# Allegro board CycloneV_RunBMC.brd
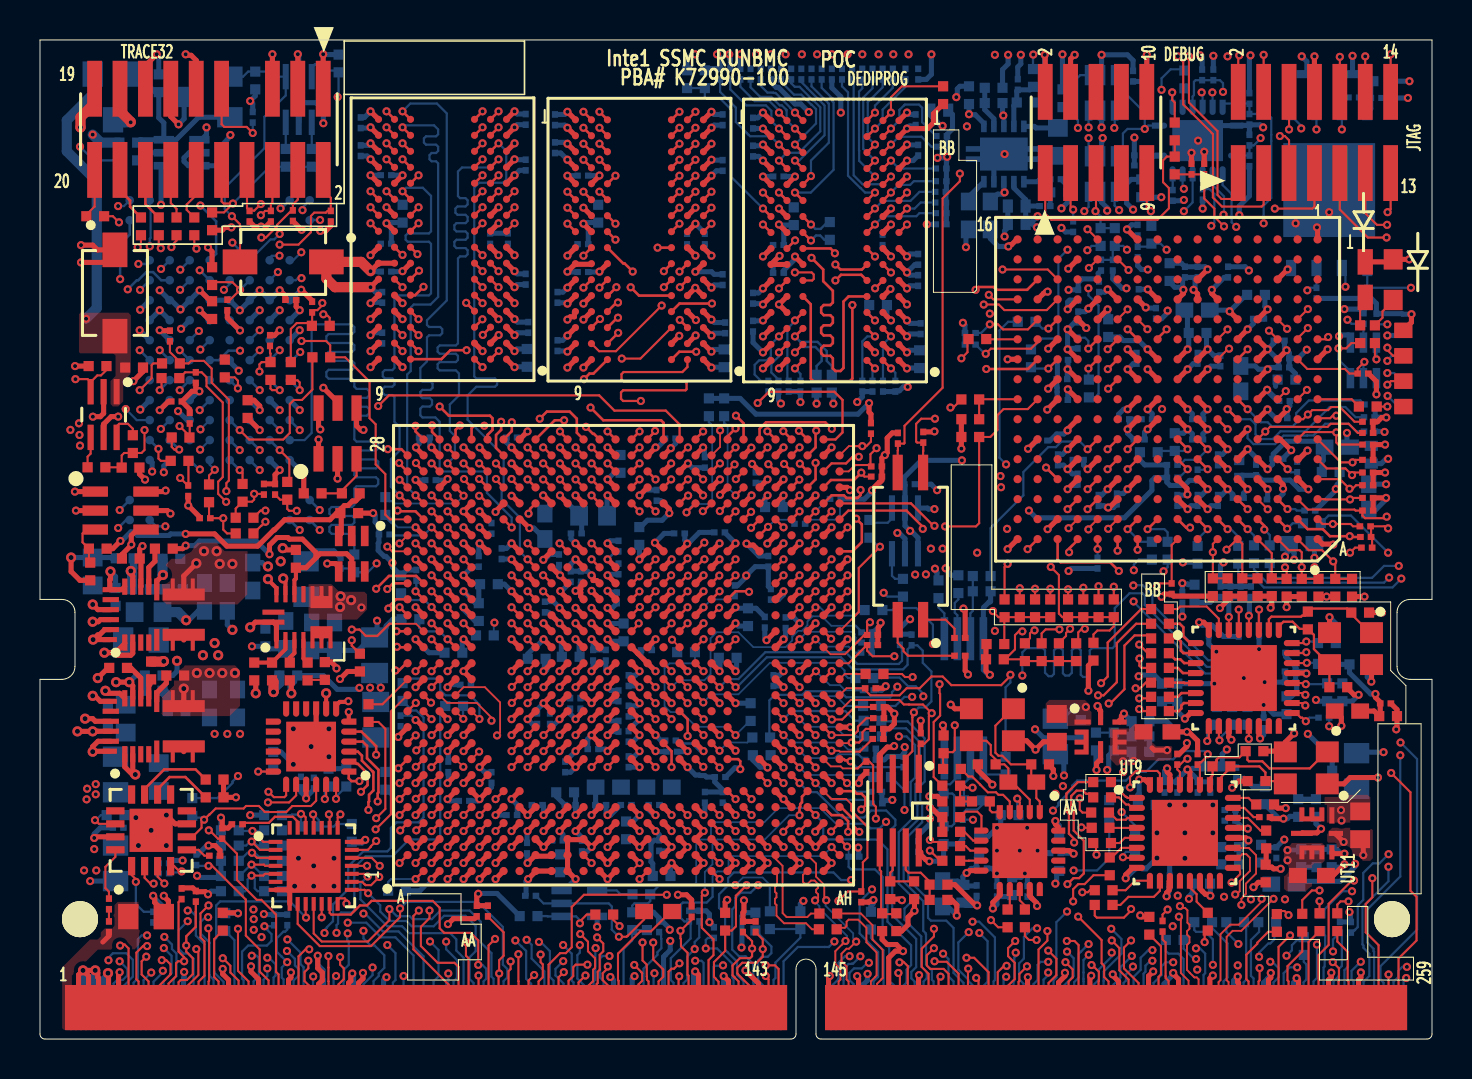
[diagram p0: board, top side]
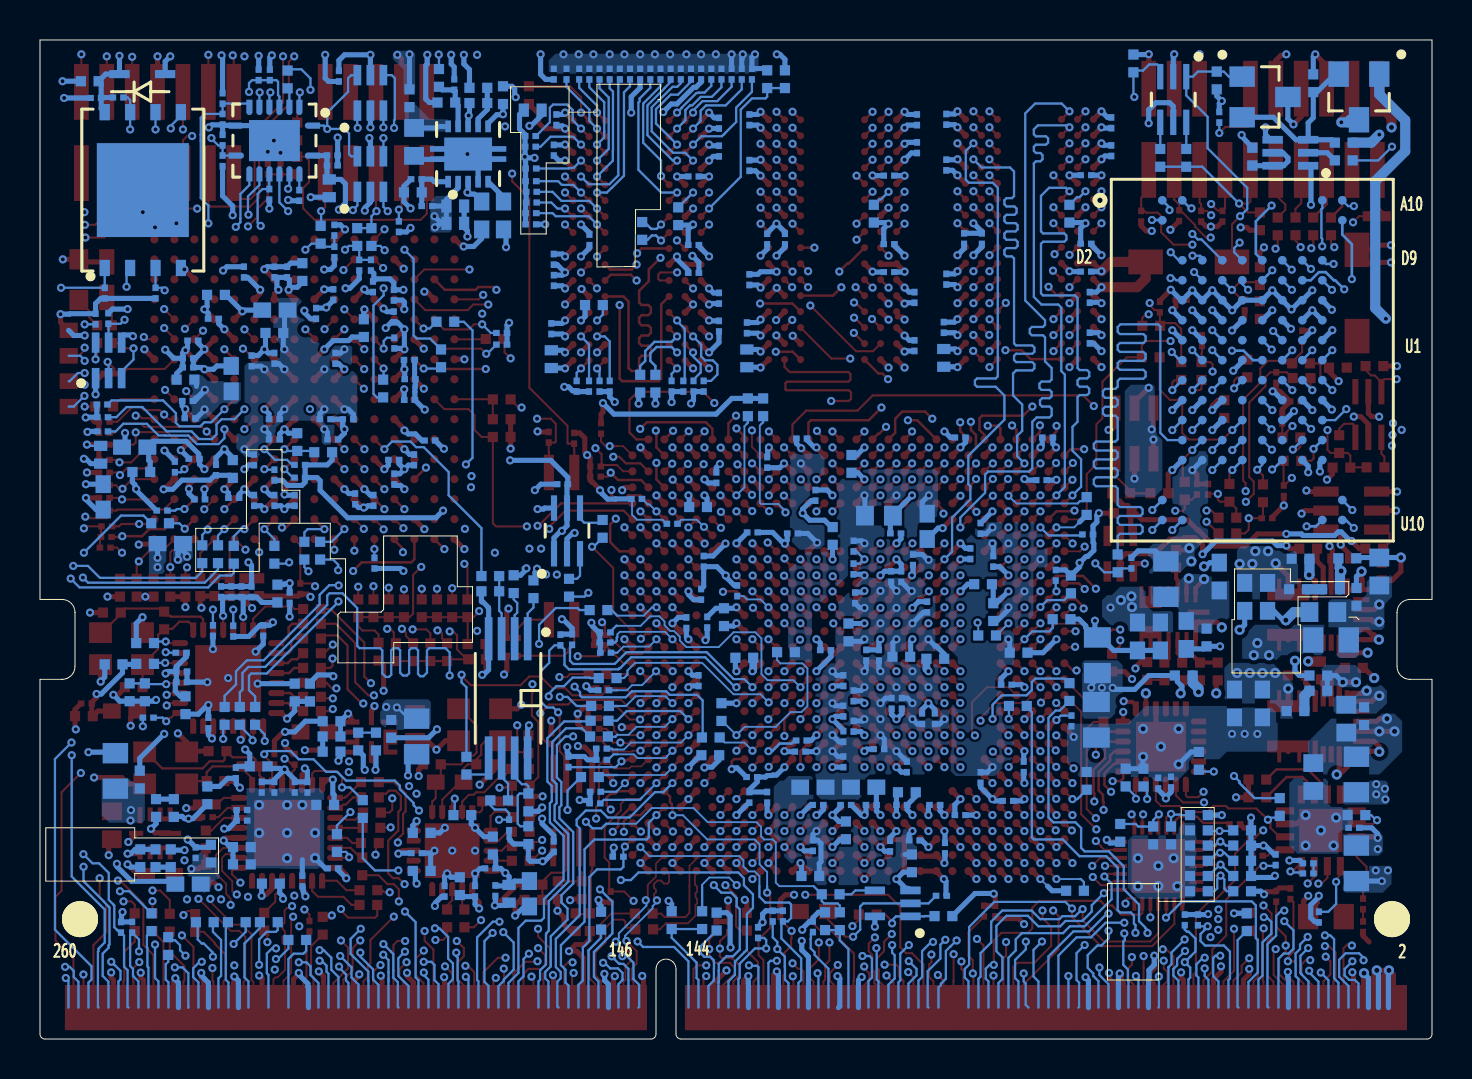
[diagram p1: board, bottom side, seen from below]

Outline 69.6 x 50 mm; copper layers: TOP, L2-GND, L3-SIG, L4-GND, L5-SIG, L6-VCC, L7-VCC, L8-SIG, L9-GND, L10-SIG, L11-GND, BOTTOM. Coordinates in mm from the lower left corner of the outline.
Outline path: 0,50 0,22 1.1,22 arc(1.56,21.81) 1.75,21.35 1.75,18.65 arc(1.56,18.19) 1.1,18 0,18 0,0.25 arc(0.07,0.07) 0.25,0 37.55,0 arc(37.73,0.07) 37.8,0.25 37.8,3.5 arc(38.3,4) 38.8,3.5 38.8,0.25 arc(38.87,0.07) 39.05,0 69.35,0 arc(69.53,0.07) 69.6,0.25 69.6,18 68.5,18 arc(68.04,18.19) 67.85,18.65 67.85,21.35 arc(68.04,21.81) 68.5,22 69.6,22 69.6,50 0,50

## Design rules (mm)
constraint set DEFAULT: min track width 0.104
net group CLK_100M_BMC_PE_D: nets CLK_100M_BMC_PE_DN CLK_100M_BMC_PE_DP
net group DIFFPAIR0: nets P2E_PCH_BMC_TX_DN P2E_PCH_BMC_TX_DP
net group DIFFPAIR1: nets P2E_PCH_BMC_RX_C_DN P2E_PCH_BMC_RX_C_DP
net group DIFFPAIR2: nets P2E_PCH_BMC_RX_DN P2E_PCH_BMC_RX_DP
net group EMMC_SMC_DAT1: nets EMMC_SMC_DAT1 EMMC_SMC_DAT1_R
net group EMMC_SMC_DAT2: nets EMMC_SMC_DAT2 EMMC_SMC_DAT2_R
net group EMMC_SMC_DAT3: nets EMMC_SMC_DAT3 EMMC_SMC_DAT3_R
net group EMMC_SMC_DAT4: nets EMMC_SMC_DAT4 EMMC_SMC_DAT4_R
net group EMMC_SMC_DAT5: nets EMMC_SMC_DAT5 EMMC_SMC_DAT5_R
net group EMMC_SMC_DAT6: nets EMMC_SMC_DAT6 EMMC_SMC_DAT6_R
net group EMMC_SMC_DAT7: nets EMMC_SMC_DAT7 EMMC_SMC_DAT7_R
net group FM_C5_FPGA_AS_DATA0: nets FM_C5_FPGA_AS_DATA0 FM_C5_FPGA_AS_DATA0_R
net group FM_C5_FPGA_DCLK: nets FM_C5_FPGA_DCLK FM_C5_FPGA_DCLK_R
net group IRQ_SMB_INTERNAL_ALERT_N: nets IRQ_SMB_INTERNAL_ALERT_N IRQ_SMB_INTERNAL_ALERT_R_N
net group JTAG_C5_FPGA_TDO: nets JTAG_C5_FPGA_TDO JTAG_C5_FPGA_TDO_R
net group JTAG_HDR_TDI: nets JTAG_HDR_TDI JTAG_M10_TDI
net group JTAG_M10_MASTER_TCK: nets JTAG_M10_MASTER_TCK JTAG_M10_MASTER_TCK_R
net group JTAG_M10_MASTER_TDI: nets JTAG_M10_MASTER_TDI JTAG_M10_MASTER_TDI_R
net group JTAG_M10_MASTER_TMS: nets JTAG_M10_MASTER_TMS JTAG_M10_MASTER_TMS_R
net group JTAG_M10_TDO: nets JTAG_M10_TDO JTAG_M10_TDO_R
net group PD_BMC_DDR3_DQS5: nets PD_BMC_DDR3_DQS5_P PU_BMC_DDR3_DQS5_N
net group RGMII_BMC_RMM4_MDC: nets RGMII_BMC_RMM4_MDC RGMII_BMC_RMM4_R_MDC
net group RGMII_BMC_RMM4_MDIO: nets RGMII_BMC_RMM4_MDIO RGMII_BMC_RMM4_R_MDIO
net group RGMII_BMC_RMM4_R_TXD_0: nets RGMII_BMC_RMM4_R_TXD_0 RGMII_BMC_RMM4_TXD_0
net group RGMII_BMC_RMM4_R_TXD_1: nets RGMII_BMC_RMM4_R_TXD_1 RGMII_BMC_RMM4_TXD_1
net group RGMII_BMC_RMM4_R_TXD_2: nets RGMII_BMC_RMM4_R_TXD_2 RGMII_BMC_RMM4_TXD_2
net group RGMII_BMC_RMM4_R_TXD_3: nets RGMII_BMC_RMM4_R_TXD_3 RGMII_BMC_RMM4_TXD_3
net group RGMII_BMC_RMM4_TX_CLK: nets RGMII_BMC_RMM4_TX_CLK RGMII_BMC_RMM4_TX_R_CLK
net group RGMII_BMC_RMM4_TX_CTRL: nets RGMII_BMC_RMM4_TX_CTRL RGMII_BMC_RMM4_TX_R_CTRL
net group SMB_C5_M10_CLK: nets SMB_C5_M10_CLK SMB_C5_M10_R_CLK
net group SMB_C5_M10_DATA: nets SMB_C5_M10_DATA SMB_C5_M10_R_DATA
net group SPI_M10_FLASH_CLK: nets SPI_M10_FLASH_CLK SPI_M10_FLASH_CLK_R
net group SPI_M10_FLASH_MISO: nets SPI_M10_FLASH_MISO SPI_M10_FLASH_MISO_R
net group SPI_M10_FLASH_MOSI: nets SPI_M10_FLASH_MOSI SPI_M10_FLASH_MOSI_R
net group TP_EMMC_STRB: nets EMMC_STRB_R TP_EMMC_STRB
net group TRC_HPS_TRACE32_D0: nets TRC_HPS_TRACE32_D0 TRC_HPS_TRACE32_D0_R
net group TRC_HPS_TRACE32_D1: nets TRC_HPS_TRACE32_D1 TRC_HPS_TRACE32_D1_R
net group TRC_HPS_TRACE32_D2: nets TRC_HPS_TRACE32_D2 TRC_HPS_TRACE32_D2_R
net group TRC_HPS_TRACE32_D3: nets TRC_HPS_TRACE32_D3 TRC_HPS_TRACE32_D3_R
net group TRC_TRACE32_CLK: nets TRC_TRACE32_CLK TRC_TRACE32_CLK_R
net group ULPI_USBPHY_PCH_CLKOUT: nets ULPI_USBPHY_PCH_CLKOUT ULPI_USBPHY_PCH_CLKOUT_R
net group ULPI_USBPHY_PCH_DATA<0>: nets ULPI_USBPHY_PCH_DATA<0> ULPI_USBPHY_PCH_R_DATA<0>
net group ULPI_USBPHY_PCH_DATA<1>: nets ULPI_USBPHY_PCH_DATA<1> ULPI_USBPHY_PCH_R_DATA<1>
net group ULPI_USBPHY_PCH_DATA<2>: nets ULPI_USBPHY_PCH_DATA<2> ULPI_USBPHY_PCH_R_DATA<2>
net group ULPI_USBPHY_PCH_DATA<3>: nets ULPI_USBPHY_PCH_DATA<3> ULPI_USBPHY_PCH_R_DATA<3>
net group ULPI_USBPHY_PCH_DATA<4>: nets ULPI_USBPHY_PCH_DATA<4> ULPI_USBPHY_PCH_R_DATA<4>
net group ULPI_USBPHY_PCH_DATA<5>: nets ULPI_USBPHY_PCH_DATA<5> ULPI_USBPHY_PCH_R_DATA<5>
net group ULPI_USBPHY_PCH_DATA<6>: nets ULPI_USBPHY_PCH_DATA<6> ULPI_USBPHY_PCH_R_DATA<6>
net group ULPI_USBPHY_PCH_DATA<7>: nets ULPI_USBPHY_PCH_DATA<7> ULPI_USBPHY_PCH_R_DATA<7>
net group ULPI_USBPHY_PCH_DIR: nets ULPI_USBPHY_PCH_DIR ULPI_USBPHY_PCH_DIR_R
net group ULPI_USBPHY_PCH_NXT: nets ULPI_USBPHY_PCH_NXT ULPI_USBPHY_PCH_NXT_R
net group ULPI_USBPHY_USB2B_CLKOUT: nets ULPI_USBPHY_USB2B_CLKOUT ULPI_USBPHY_USB2B_CLKOUT_R
net group ULPI_USBPHY_USB2B_DATA<0>: nets ULPI_USBPHY_USB2B_DATA<0> ULPI_USBPHY_USB2B_R_DATA<0>
net group ULPI_USBPHY_USB2B_DATA<1>: nets ULPI_USBPHY_USB2B_DATA<1> ULPI_USBPHY_USB2B_R_DATA<1>
net group ULPI_USBPHY_USB2B_DATA<2>: nets ULPI_USBPHY_USB2B_DATA<2> ULPI_USBPHY_USB2B_R_DATA<2>
net group ULPI_USBPHY_USB2B_DATA<3>: nets ULPI_USBPHY_USB2B_DATA<3> ULPI_USBPHY_USB2B_R_DATA<3>
net group ULPI_USBPHY_USB2B_DATA<4>: nets ULPI_USBPHY_USB2B_DATA<4> ULPI_USBPHY_USB2B_R_DATA<4>
net group ULPI_USBPHY_USB2B_DATA<5>: nets ULPI_USBPHY_USB2B_DATA<5> ULPI_USBPHY_USB2B_R_DATA<5>
net group ULPI_USBPHY_USB2B_DATA<6>: nets ULPI_USBPHY_USB2B_DATA<6> ULPI_USBPHY_USB2B_R_DATA<6>
net group ULPI_USBPHY_USB2B_DATA<7>: nets ULPI_USBPHY_USB2B_DATA<7> ULPI_USBPHY_USB2B_R_DATA<7>
net group ULPI_USBPHY_USB2B_DIR: nets ULPI_USBPHY_USB2B_DIR ULPI_USBPHY_USB2B_DIR_R
net group ULPI_USBPHY_USB2B_NXT: nets ULPI_USBPHY_USB2B_NXT ULPI_USBPHY_USB2B_NXT_R
net group USB2_PCH_SMC: nets USB2_PCH_SMC_DN USB2_PCH_SMC_DP
net group USB2_USB2B_D: nets USB2_USB2B_DN USB2_USB2B_DP
net group BANK-3B: nets CLK_50M_C5_FPGA DBG_XDP_SYSPWROK_HOOK3 DBP_DEBUG_EN_N DBP_JUMPER_EN_DET DBP_PRDY_N DBP_PREQ_N DBP_PWR_DEBUG_HOOK2_N DBP_SMC_NTRST_N DBP_SMC_TCK_R DBP_SMC_TDI_R DBP_SMC_TDO DBP_SMC_TMS_R DBP_TCK_MUX_SEL DBP_XDP_PRSNT_N FM_BMC_PWRBTN_OUT_N FM_LED_BEEP_BMC FM_TPM_EN_PULSE FP_ID_BTN_N FP_ID_LED_N FP_LED_STATUS_AMBER_N FP_LED_STATUS_GREEN_N FP_NMI_BTN_N FP_PWR_BTN_N FP_RST_BTN_N RST_BMC_RSTBTN_OUT_N
net group BANK-4A: nets FM_BIOS_POST_CMPLT_N FM_BMC_ONCTL_R_N FM_CPU_BMC_MSMI_CATERR_LVT3_N FM_CPU_BMCINIT FM_CPU_ERR2_LVT3_N FM_PCH_BMC_THERMTRIP_N FM_PVCCIN_CPU0_PWR_IN_ALERT_N FM_PVCCIN_CPU1_PWR_IN_ALERT_N FM_SLPS4_N IRQ_BMC_PCH_NMI IRQ_BMC_PCH_SCI_LPC_R_N IRQ_BMC_PCH_SMI_LPC_N IRQ_NMI_EVENT_N IRQ_SMI_ACTIVE_N PECI_SMC_IN_LVC33 PECI_SMC_OUT_N PWRGD_CPU0_LVC3 PWRGD_PS_PWROK_PLD_BMC RST_PLTRST_MONITOR_N RST_SMC_SMB_MUX_RST_N SGPIO_SMC_CPLD_CLK SGPIO_SMC_CPLD_DIN SGPIO_SMC_CPLD_LD_N SMB_BATPAK_DATA SMB_BMC2BMC_CLK SMB_BMC2BMC_DATA SMB_HOST_LVC3_CLK SMB_HSBP_LVC3_CLK SMB_HSBP_LVC3_DATA SMB_IPMB_LVC3_DATA SMB_PCIE_LVC3_CLK SMB_PCIE_LVC3_DATA SMB_PMBUS_LVC3_CLK SMB_PMBUS_LVC3_DATA SMB_RSSD_15_8_CLK SMB_RSSD_15_8_DATA SMB_SMLINK0_LVC3_CLK SMB_SMLINK0_LVC3_DATA SMB_TEMP_SENSOR_LVC3_CLK SMB_TEMP_SENSOR_LVC3_DATA
net group CLK: nets CLK_25M_HPS_CLK1 CLK_25M_HPS_CLK1_R CLK_25M_HPS_CLK2 CLK_25M_HPS_CLK2_R CLK_25M_M10 CLK_25M_M10_R CLK_50M_C5_FPGA_R
net group DDR_ADD: nets V_M_BMC_DDR3_RST_N
net group EMMC_SMC_CLK: nets EMMC_SMC_CLK EMMC_SMC_CLK_CONN EMMC_SMC_CLK_R
net group EMMC_SMC_CMD: nets EMMC_SMC_CMD EMMC_SMC_CMD_CONN EMMC_SMC_CMD_R
net group EMMC_SMC_DAT0_R: nets EMMC_SMC_DAT0 EMMC_SMC_DAT0_CONN EMMC_SMC_DAT0_R
net group EU9: nets ISENSE_P3V3_N ISENSE_P3V3_P ISENSE_P12V_C ISENSE_P12V_N ISENSE_P12V_P PD_TELEMETRY_ADDR PU_TELEMETRY_ENA PU_TELEMETRY_SHTDN
net group FM_C5_M10_RSVD: nets FM_C5_M10_RSVD<0> FM_C5_M10_RSVD<1> FM_C5_M10_RSVD<2> FM_C5_M10_RSVD<3>
net group FM_M10_EDGE_RSVD: nets DBG_RSMRST_MONITOR_N FM_M10_EDGE_RSVD<2> FM_M10_EDGE_RSVD<3> FM_M10_EDGE_RSVD<4> FM_M10_EDGE_RSVD<5> FM_M10_EDGE_RSVD<6> FM_M10_EDGE_RSVD<7>
net group FM_VGA_B: nets FM_VGA_B<0> FM_VGA_B<1> FM_VGA_B<2> FM_VGA_B<3>
net group FM_VGA_G: nets FM_VGA_G<0> FM_VGA_G<1> FM_VGA_G<2> FM_VGA_G<3>
net group FM_VGA_R: nets FM_VGA_R<0> FM_VGA_R<1> FM_VGA_R<2> FM_VGA_R<3>
net group JTAG_HDR_SW_TCK: nets JTAG_HDR_SW_TCK JTAG_HDR_TCK JTAG_M10_TCK
net group JTAG_HDR_SW_TMS: nets JTAG_HDR_SW_TMS JTAG_HDR_TMS JTAG_M10_TMS
net group NC_EMMC: nets NC_EMMC<0> NC_EMMC<1> NC_EMMC<2> NC_EMMC<3> NC_EMMC<4> NC_EMMC<5> NC_EMMC<6> NC_EMMC<7> NC_EMMC<8> NC_EMMC<9> NC_EMMC<10> NC_EMMC<11>
net group NC_EMMC_RFU: nets NC_EMMC_RFU<0> NC_EMMC_RFU<1> NC_EMMC_RFU<2> NC_EMMC_RFU<3> NC_EMMC_RFU<4> NC_EMMC_RFU<5> NC_EMMC_RFU<6> NC_EMMC_RFU<7> NC_EMMC_RFU<8> NC_EMMC_RFU<9> NC_EMMC_RFU<10> NC_EMMC_RFU<11> NC_EMMC_RFU<12> NC_EMMC_RFU<13> NC_EMMC_RFU<14> NC_EMMC_RFU<15> NC_EMMC_RFU<16> NC_EMMC_RFU<17> NC_EMMC_RFU<18> NC_EMMC_RFU<19> NC_EMMC_RFU<20> NC_EMMC_RFU<21> NC_EMMC_RFU<22> NC_EMMC_RFU<23> NC_EMMC_RFU<24> NC_EMMC_RFU<25> NC_EMMC_RFU<26> NC_EMMC_RFU<27> NC_EMMC_RFU<28> NC_EMMC_RFU<29> NC_EMMC_RFU<30> NC_EMMC_RFU<31> NC_EMMC_RFU<32> NC_EMMC_RFU<33> NC_EMMC_RFU<34> NC_EMMC_RFU<35> NC_EMMC_RFU<36> NC_EMMC_RFU<37> NC_EMMC_RFU<38> NC_EMMC_RFU<39> NC_EMMC_RFU<40> NC_EMMC_RFU<41>
net group PD_V_M_DDR3_DQU: nets PD_V_M_DDR3_DQU<0> PD_V_M_DDR3_DQU<1> PD_V_M_DDR3_DQU<2> PD_V_M_DDR3_DQU<3> PD_V_M_DDR3_DQU<4> PD_V_M_DDR3_DQU<5> PD_V_M_DDR3_DQU<6> PD_V_M_DDR3_DQU<7>
net group PECI_SMC_S_R: nets PECI_SMC PECI_SMC_IN PECI_SMC_OUT_B PECI_SMC_S_R
net group PWRGD_SMC_AUX_VRS_R2: nets PWRGD_BMC_AUX_VRS PWRGD_P0V75_AUX_R PWRGD_SMC_AUX_VRS_R2
net group RMII: nets RMII_BMC_NIC_TX_EN RMII_BMC_NIC_TX_R_EN RMII_BMC_NIC_TXD_0 RMII_BMC_NIC_TXD_0_R RMII_BMC_NIC_TXD_1 RMII_BMC_NIC_TXD_1_R RMII_NIC_BMC_CRS_DV RMII_NIC_BMC_CRS_R_DV RMII_NIC_BMC_RXD_0 RMII_NIC_BMC_RXD_1 RMII_NIC_BMC_RXD_R_0 RMII_NIC_BMC_RXD_R_1
net group RST_EMMC_SMC_R_N: nets RST_EMMC_SMC_R_N RST_HPS_RST_N RST_HPS_RST_R1_N RST_HPS_RST_R2_N
net group SMB_INTERNAL_CLK_R2: nets SMB_INTERNAL_CLK SMB_INTERNAL_CLK_R2 SMB_INTERNAL_R_CLK
net group SMB_INTERNAL_DATA: nets SMB_INTERNAL_DATA SMB_INTERNAL_DATA_R2 SMB_INTERNAL_R_DATA
net group SPI_M10_FLASH_CS0_N: nets FM_DEDI_IO3 FM_M10_DEV_CLR_N P3V3_AUX_SPI SPI_M10_FLASH_CS0__RN SPI_M10_FLASH_CS0_N SPI_M10_FLASH_IO2_WP_N SPI_M10_FLASH_IO2_WP_R_N SPI_M10_FLASH_IO3_HD_N SPI_M10_FLASH_IO3_HD_R_N

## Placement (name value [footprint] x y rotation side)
C1A6  0.1uF  [SMC0201A]  45.32 40.77 90 bottom
C1A7  0.1uF  [SMC0201A]  39.59 48.56 180 bottom
C1A8  0.1uF  [SMC0201A]  36.54 48.56 180 bottom
C2L16  0.1uF  [SMC0201A]  56.48 7.64 0 bottom
C2L17  2.2uF  [SMC0402A]  54.9 11.71 270 bottom
C2L18  0.1uF  [SMC0201A]  54.69 8.54 270 bottom
C2L24  0.1uF  [SMC0201A]  56.86 12.87 180 bottom
C2L25  0.1uF  [SMC0201A]  57.88 12.87 180 bottom
C2L26  0.1uF  [SMC0201A]  58.51 12.87 180 bottom
C2L31  0.1uF  [SMC0201A]  56.23 12.87 180 bottom
C2L34  0.1uF  [SMC0201A]  59.81 13.58 180 bottom
C3L11  2.2uF  [SMC0402A]  61.28 8.73 0 top
C5C1  0.1uF  [SMC0201A]  46.82 8.54 270 bottom
C5C2  0.1uF  [SMC0201A]  46.83 7.69 180 bottom
C5C5  NA  [SMC0402A]  49.56 13.75 90 top
C5C6  NA  [SMC0402A]  47.78 13.75 270 top
C5C7  10uF  [SMC0402B]  46.15 7.71 270 bottom
C5C8  0.1uF  [SMC0201A]  47.85 7.13 0 bottom
C5C13  0.1uF  [SMC0201A]  49.37 7.13 0 bottom
C5N17  0.1uF  [SMC0201A]  51.03 9.3 90 bottom
C7A14  2.2uF  [SMC0402A]  59.95 9.61 90 bottom
C7A15  1.0uF  [SMC0402A]  59.95 8.74 90 bottom
C7A16  22.0pF  [SMC0402A]  61.27 12.91 270 top
C7A17  22.0pF  [SMC0402A]  60.28 14.41 90 top
C8A30  0.1uF  [SMC0201A]  59.77 10.93 90 bottom
C8A31  0.1uF  [SMC0201A]  59.77 11.46 90 bottom
C8A32  2.2uF  [SMC0402A]  61.23 11.75 0 bottom
C8F1  10uF  [SMC0402B]  49.28 40.82 180 bottom
C8F2  22uF  [SMC0603A]  47.52 41.92 180 bottom
C8F3  10uF  [SMC0402B]  49.28 41.69 180 bottom
C8F4  1.0uF  [SMC0402A]  50.51 42.37 270 bottom
C8F5  4.7uF  [SMC0603C]  50.89 45.6 270 bottom
C8F6  0.1uF  [SMC0402A]  46.45 46.79 0 bottom
C8F7  1000pF  [SMC0402A]  48.84 46.87 270 bottom
C8F8  1000pF  [SMC0402A]  47.24 46.84 270 bottom
C9L13  0.1uF  [SMC0201A]  43.91 48.56 180 bottom
C107  10uF  [SMC0603C]  50.84 16.27 270 top
C114  10uF  [SMC0603C]  66.01 11.4 270 top
C305  2.2uF  [SMC0402A]  65.47 18.75 270 bottom
C306  22.0pF  [SMC0402A]  64.47 17.61 90 top
C307  22.0pF  [SMC0402A]  65.56 21.34 90 top
C308  0.1uF  [SMC0201A]  57.12 22.36 180 bottom
C309  0.1uF  [SMC0201A]  62.78 17.86 90 bottom
C310  0.1uF  [SMC0201A]  62.78 18.4 90 bottom
C311  2.2uF  [SMC0402A]  62.32 17.15 180 bottom
C312  0.1uF  [SMC0201A]  59.02 22.12 0 bottom
C313  0.1uF  [SMC0201A]  59.53 22.12 0 bottom
C314  0.1uF  [SMC0201A]  60.04 22.12 0 bottom
C315  0.1uF  [SMC0201A]  60.55 22.12 0 bottom
C316  0.1uF  [SMC0201A]  61.18 15.55 0 bottom
C317  0.1uF  [SMC0201A]  58.44 20.71 180 bottom
C318  2.2uF  [SMC0402A]  56.86 16.9 0 bottom
C319  1.0uF  [SMC0402A]  64.36 17.8 180 bottom
C320  2.2uF  [SMC0402A]  65.12 17.8 180 bottom
C321  1.0uF  [SMC0402A]  66.96 16.16 90 top
C322  0.1uF  [SMC0201A]  67.01 16.79 90 top
CB1  0.1uF  [SMC0402A]  5.94 47.39 0 bottom
CB2  10pF  [SMC0201A]  54.88 40.21 0 bottom
CB3  10uF  [SMC0402B]  45.41 46.49 180 bottom
CB4  0.1uF  [SMC0201A]  24.29 45.76 0 bottom
CB5  0.1uF  [SMC0201A]  43.78 45.74 0 bottom
CB6  0.1uF  [SMC0201A]  34.13 45.74 0 bottom
CB7  0.1uF  [SMC0201A]  25.75 45.74 0 bottom
CB8  0.1uF  [SMC0201A]  16.04 45.59 0 bottom
CB9  0.1uF  [SMC0201A]  35.65 45.57 0 bottom
CB10  0.1uF  [SMC0201A]  25.75 44.34 0 bottom
CB11  0.1uF  [SMC0201A]  43.91 44.21 0 bottom
CB12  0.1uF  [SMC0201A]  16.04 44.19 0 bottom
CB13  0.1uF  [SMC0201A]  35.65 44.17 0 bottom
CB14  1.0uF  [SMC0402A]  66.67 47.94 270 bottom
CB15  0.1uF  [SMC0201A]  24.29 44.01 180 bottom
CB16  0.1uF  [SMC0201A]  34.13 43.99 180 bottom
CB17  10pF  [SMC0201A]  53.05 38.99 180 bottom
CB18  0.01uF  [SMC0201A]  66.54 47.1 270 bottom
CB19  0.1uF  [SMC0201A]  17.57 43.23 90 bottom
CB20  0.1uF  [SMC0201A]  27.41 43.21 90 bottom
CB21  0.1uF  [SMC0201A]  37.19 43.17 90 bottom
CB22  10pF  [SMC0201A]  58.67 47.99 0 bottom
CB23  10pF  [SMC0201A]  60.47 46.3 180 bottom
CB24  0.01uF  [SMC0201A]  23.4 39.79 0 bottom
CB25  0.1uF  [SMC0201A]  22.51 39.79 0 bottom
CB26  0.01uF  [SMC0201A]  33.24 39.77 0 bottom
CB27  0.1uF  [SMC0201A]  32.35 39.77 0 bottom
CB28  0.1uF  [SMC0201A]  42.13 39.73 0 bottom
CB29  0.1uF  [SMC0201A]  17.03 39.8 270 bottom
CB30  0.1uF  [SMC0201A]  26.88 39.78 270 bottom
CB31  0.1uF  [SMC0201A]  36.66 39.74 270 bottom
CB32  0.01uF  [SMC0201A]  43.91 39.29 180 bottom
CB33  10pF  [SMC0201A]  60.47 44.72 0 bottom
CB34  0.1uF  [SMC0201A]  17.57 38.41 90 bottom
CB35  0.1uF  [SMC0201A]  27.41 38.38 90 bottom
CB36  0.1uF  [SMC0201A]  55.25 44.23 90 bottom
CB37  0.1uF  [SMC0201A]  37.19 38.34 90 bottom
CB38  0.1uF  [SMC0201A]  24.29 37.76 0 bottom
CB39  0.1uF  [SMC0201A]  34.13 37.74 0 bottom
CB40  0.1uF  [SMC0201A]  43.91 37.7 0 bottom
CB41  0.1uF  [SMC0201A]  54.65 48.46 180 bottom
CB42  0.1uF  [SMC0201A]  25.88 36.85 0 bottom
CB43  0.1uF  [SMC0201A]  17.11 36.85 0 bottom
CB44  0.1uF  [SMC0201A]  35.65 36.81 0 bottom
CB45  0.1uF  [SMC0201A]  35.65 35.94 180 bottom
CB46  0.1uF  [SMC0201A]  24.41 35.35 0 bottom
CB47  0.1uF  [SMC0201A]  34.26 35.32 0 bottom
CB48  0.1uF  [SMC0201A]  44.03 35.28 0 bottom
CB49  0.1uF  [SMC0201A]  17.11 35.35 180 bottom
CB50  0.1uF  [SMC0201A]  25.88 34.97 180 bottom
CB51  10pF  [SMC0201A]  51.66 40.92 180 bottom
CB52  10uF  [SMC0402B]  24.41 33.64 90 bottom
CB53  10uF  [SMC0402B]  34.26 33.62 90 bottom
CB54  10uF  [SMC0402B]  44.03 33.58 90 bottom
CB55  10pF  [SMC0201A]  58.21 43.27 180 top
CB56  0.1uF  [SMC0201A]  59.4 38.12 0 bottom
CB57  0.1uF  [SMC0201A]  57.88 38.12 0 bottom
CB58  0.1uF  [SMC0201A]  57.24 38.12 0 bottom
CB59  2.2uF  [SMC0402A]  56.48 37.94 0 bottom
CB60  0.1uF  [SMC0201A]  55.8 36.58 180 bottom
CB61  0.1uF  [SMC0201A]  52.95 37.38 0 bottom
CB62  0.1uF  [SMC0201A]  51.91 36.96 0 bottom
CB63  2.2uF  [SMC0402A]  60.36 37.24 270 bottom
CB64  0.1uF  [SMC0201A]  54.93 36.99 0 bottom
CB65  2.2uF  [SMC0402A]  53.41 36.02 180 bottom
CB66  0.1uF  [SMC0201A]  23.86 30.1 90 bottom
CB67  0.1uF  [SMC0201A]  19.49 30.1 90 bottom
CB68  0.1uF  [SMC0201A]  31.25 30.05 270 bottom
CB69  0.1uF  [SMC0201A]  60.66 36.05 270 bottom
CB70  0.1uF  [SMC0201A]  51.91 35.87 0 bottom
CB71  2.2uF  [SMC0402A]  57.44 35.34 270 bottom
CB72  0.1uF  [SMC0201A]  61.69 34.96 270 bottom
CB73  0.01uF  [SMC0201A]  33.24 29.13 180 bottom
CB74  1.0uF  [SMC0402A]  29.03 29.23 180 bottom
CB75  0.1uF  [SMC0201A]  51.4 33.99 90 bottom
CB76  0.01uF  [SMC0201A]  35.78 27.83 0 bottom
CB77  0.01uF  [SMC0201A]  19.79 27.97 90 bottom
CB78  0.1uF  [SMC0201A]  61.93 34.07 270 bottom
CB79  0.1uF  [SMC0201A]  57.88 33.8 0 bottom
CB80  0.1uF  [SMC0201A]  54.83 34.33 180 bottom
CB81  0.1uF  [SMC0201A]  43.21 27.77 270 bottom
CB82  0.1uF  [SMC0201A]  59.02 33.67 0 bottom
CB83  0.1uF  [SMC0201A]  61.93 33.61 270 bottom
CB84  0.1uF  [SMC0201A]  30.83 27.48 180 bottom
CB85  0.1uF  [SMC0201A]  51.36 33.03 90 bottom
CB86  2.2uF  [SMC0402A]  61.88 33 270 bottom
CB87  4.7uF  [SMC0603C]  28.35 26.19 180 bottom
CB88  0.1uF  [SMC0201A]  61.96 31.93 270 bottom
CB89  0.1uF  [SMC0201A]  51.39 31.98 90 bottom
CB90  0.01uF  [SMC0201A]  22.57 25.29 0 bottom
CB91  0.1uF  [SMC0201A]  66.22 31.76 270 bottom
CB92  0.01uF  [SMC0201A]  34.25 25.35 90 bottom
CB93  0.01uF  [SMC0201A]  31.71 25.3 270 bottom
CB94  0.01uF  [SMC0201A]  26.55 25.3 270 bottom
CB95  0.47uF  [SMC0402A]  29.97 24.73 0 bottom
CB96  0.1uF  [SMC0201A]  66.2 31.12 270 bottom
CB97  0.1uF  [SMC0201A]  61.83 31.07 270 bottom
CB98  0.1uF  [SMC0201A]  57.61 31.02 270 bottom
CB99  0.1uF  [SMC0201A]  55.61 31.02 90 bottom
CB100  0.1uF  [SMC0201A]  53.93 31.02 270 bottom
CB101  0.1uF  [SMC0201A]  28.92 24.94 180 bottom
CB102  0.01uF  [SMC0201A]  23.08 24.55 180 bottom
CB103  0.1uF  [SMC0201A]  66.2 30.41 270 bottom
CB104  0.1uF  [SMC0201A]  25.95 24.25 180 bottom
CB105  0.01uF  [SMC0201A]  36.42 24.17 180 bottom
CB106  0.01uF  [SMC0201A]  34.74 22.17 0 bottom
CB107  0.01uF  [SMC0201A]  21.94 24.17 180 bottom
CB108  0.1uF  [SMC0201A]  58.15 30 90 bottom
CB109  0.1uF  [SMC0201A]  55.23 30 90 bottom
CB110  0.1uF  [SMC0201A]  50.37 29.95 90 bottom
CB111  0.01uF  [SMC0201A]  28.92 23.26 0 bottom
CB112  10uF  [SMC0603C]  2.63 22.7 90 bottom
CB113  0.01uF  [SMC0201A]  27.04 22.88 0 bottom
CB114  0.01uF  [SMC0201A]  26.54 22.88 0 bottom
CB115  22uF  [SMC0603A]  10.64 22.45 0 bottom
CB116  0.1uF  [SMC0201A]  61.63 29.04 270 bottom
CB117  0.1uF  [SMC0201A]  58.9 29.25 180 bottom
CB118  0.1uF  [SMC0201A]  52.18 28.99 90 bottom
CB119  0.1uF  [SMC0201A]  50.89 29.25 180 bottom
CB120  0.1uF  [SMC0201A]  62.86 28.36 0 bottom
CB121  1.0uF  [SMC0402A]  59.96 28.97 180 bottom
CB122  0.1uF  [SMC0201A]  60.8 28.75 180 bottom
CB123  0.01uF  [SMC0201A]  36.54 21.99 0 bottom
CB124  1.0uF  [SMC0402A]  64.09 28.38 270 bottom
CB125  22uF  [SMC0603A]  9.37 22.83 180 bottom
CB126  22uF  [SMC0603A]  8.22 22.83 180 bottom
CB127  0.1uF  [SMC0402A]  3.78 21.68 0 bottom
CB128  0.1uF  [SMC0201A]  28.85 21.81 0 bottom
CB129  0.1uF  [SMC0201A]  51.89 27.76 0 bottom
CB130  0.01uF  [SMC0201A]  25.24 21.35 0 bottom
CB131  10uF  [SMC0603C]  4.73 21.37 0 bottom
CB132  1.0uF  [SMC0402A]  35.4 20.67 0 bottom
CB133  0.1uF  [SMC0201A]  60.18 27.08 90 bottom
CB134  0.01uF  [SMC0201A]  36.24 20.59 0 bottom
CB135  0.01uF  [SMC0201A]  37.28 20.57 0 bottom
CB136  0.1uF  [SMC0201A]  53.84 27.3 180 bottom
CB137  0.1uF  [SMC0201A]  61.35 27.01 270 bottom
CB138  0.1uF  [SMC0201A]  58.9 26.69 0 bottom
CB139  0.1uF  [SMC0201A]  57.88 27.22 180 bottom
CB140  0.1uF  [SMC0201A]  56.86 27.22 180 bottom
CB141  0.1uF  [SMC0201A]  52.93 27.22 180 bottom
CB142  2.2uF  [SMC0402A]  29.18 19.91 0 bottom
CB143  0.1uF  [SMC0201A]  63.23 26.45 270 bottom
CB144  22uF  [SMC0603A]  12.29 20.92 180 bottom
CB145  22uF  [SMC0603A]  14.73 20.85 180 bottom
CB146  22uF  [SMC0603A]  13.58 20.85 180 bottom
CB147  0.1uF  [SMC0402A]  11.27 20.54 180 bottom
CB148  22nF  [SMC0201A]  30.59 19.46 90 bottom
CB149  0.47uF  [SMC0402A]  21.11 19.33 90 bottom
CB150  0.01uF  [SMC0201A]  28.29 18.94 0 bottom
CB151  22nF  [SMC0201A]  27.65 18.94 0 bottom
CB152  100uF  [SMC0805C]  16.73 18.32 90 bottom
CB153  0.220uF  [SMC0402A]  26.98 19.13 90 bottom
CB154  1.0uF  [SMC0402A]  34.83 19.08 90 bottom
CB155  0.220uF  [SMC0402A]  24.39 19.03 270 bottom
CB156  0.01uF  [SMC0201A]  36.67 17.67 0 bottom
CB157  22nF  [SMC0201A]  29.43 18.2 180 bottom
CB158  0.01uF  [SMC0201A]  21.55 17.73 90 bottom
CB159  22nF  [SMC0201A]  28.92 17.44 180 bottom
CB160  10uF  [SMC0402B]  66.57 28.8 90 bottom
CB161  0.01uF  [SMC0201A]  27.02 17.06 180 bottom
CB162  0.01uF  [SMC0201A]  26.51 17.06 180 bottom
CB163  22uF  [SMC0603A]  9.87 17.49 180 bottom
CB164  22uF  [SMC0603A]  8.48 17.49 180 bottom
CB165  0.01uF  [SMC0201A]  29.43 16.68 180 bottom
CB166  0.1uF  [SMC0402A]  3.4 15.72 0 bottom
CB167  22nF  [SMC0201A]  25.49 15.77 0 bottom
CB168  22nF  [SMC0201A]  24.86 15.77 0 bottom
CB169  10uF  [SMC0603C]  4.29 15.33 90 bottom
CB170  0.01uF  [SMC0201A]  18.03 16.19 180 bottom
CB171  100uF  [SMC0805C]  16.78 16.87 270 bottom
CB172  0.1uF  [SMC0201A]  28.92 15.92 180 bottom
CB173  0.1uF  [SMC0402A]  52.04 15.97 180 bottom
CB174  22nF  [SMC0201A]  29.43 14.88 0 bottom
CB175  0.01uF  [SMC0201A]  27.39 14.51 270 bottom
CB176  22nF  [SMC0201A]  31.32 14.38 270 bottom
CB177  0.47uF  [SMC0402A]  35.64 14.2 270 bottom
CB178  22nF  [SMC0201A]  29.43 14.14 180 bottom
CB179  0.1uF  [SMC0201A]  31.79 14.94 90 bottom
CB180  22nF  [SMC0201A]  26.26 13.89 180 bottom
CB181  0.01uF  [SMC0201A]  20.41 13.35 0 bottom
CB182  10uF  [SMC0603C]  5.94 13.81 270 bottom
CB183  0.01uF  [SMC0201A]  22.57 13.35 180 bottom
CB184  0.1uF  [SMC0402A]  64.61 12.54 0 bottom
CB185  0.1uF  [SMC0201A]  13.05 12.59 0 bottom
CB186  0.1uF  [SMC0201A]  13.69 12.54 0 bottom
CB187  1.0uF  [SMC0402A]  26.7 12.35 90 bottom
CB188  0.1uF  [SMC0201A]  34.13 11.83 0 bottom
CB189  0.01uF  [SMC0201A]  33.24 11.83 0 bottom
CB190  0.01uF  [SMC0201A]  20.94 11.92 270 bottom
CB191  22nF  [SMC0201A]  30.44 11.71 270 bottom
CB192  0.01uF  [SMC0201A]  29.57 11.71 90 bottom
CB193  0.01uF  [SMC0201A]  27.77 11.71 270 bottom
CB194  22nF  [SMC0201A]  26.78 11.71 90 bottom
CB195  0.01uF  [SMC0201A]  25.13 11.71 90 bottom
CB196  0.01uF  [SMC0201A]  23.32 11.21 270 bottom
CB197  0.1uF  [SMC0201A]  3.64 10.57 270 bottom
CB198  0.47uF  [SMC0402A]  29.3 10.89 180 bottom
CB199  1.0uF  [SMC0402A]  50.96 10.32 90 bottom
CB200  0.01uF  [SMC0201A]  26.14 9.94 90 bottom
CB201  1.0uF  [SMC0402A]  46.96 9.24 0 bottom
CB202  22nF  [SMC0201A]  30.96 9.95 180 bottom
CB203  0.01uF  [SMC0201A]  27.1 9.92 180 bottom
CB204  0.1uF  [SMC0201A]  43.91 9.37 0 bottom
CB205  0.01uF  [SMC0201A]  24.35 9.82 180 bottom
CB206  0.1uF  [SMC0201A]  61.82 9.06 0 bottom
CB207  1.0uF  [SMC0402A]  61.05 8.83 0 bottom
CB208  1.0uF  [SMC0402A]  26 9.24 180 bottom
CB209  1.0uF  [SMC0402A]  50.96 8.41 90 bottom
CB210  0.1uF  [SMC0201A]  5.92 8.29 270 bottom
CB211  0.47uF  [SMC0402A]  30.64 8.16 270 bottom
CB212  1.0uF  [SMC0402A]  48.61 7.21 0 bottom
CB213  0.1uF  [SMC0201A]  24.8 7.17 90 bottom
CRB1  -  [SOD323A]  65.63 48.29 90 bottom
CT1  10uF  [SMC0402B]  55.14 43.02 270 bottom
CT2  0.1uF  [SMC0201A]  55.25 43.72 90 bottom
CT3  1.0uF  [SMC0402A]  8.6 37.74 180 top
CT4  0.1uF  [SMC0201A]  12.27 36.99 90 top
CT5  0.1uF  [SMC0201A]  9.37 37 0 top
CT6  2.2uF  [SMC0402A]  8.6 36.92 0 top
CT7  10pF  [SMC0201A]  58.13 42.54 180 bottom
CT8  0.1uF  [SMC0201A]  7.09 31.91 270 top
CT9  2.2uF  [SMC0402A]  10.38 31.97 0 top
CT10  1.0uF  [SMC0402A]  14.08 27.31 270 top
CT11  0.1uF  [SMC0201A]  66.12 30.89 90 top
CT12  0.1uF  [SMC0201A]  66.12 30.33 90 top
CT13  0.1uF  [SMC0201A]  66.12 29.75 90 top
CT14  1.0uF  [SMC0402A]  2.51 23.84 0 top
CT15  0.1uF  [SMC0201A]  66.12 28.99 90 top
CT16  0.1uF  [SMC0201A]  66.12 28.35 90 top
CT17  0.1uF  [SMC0201A]  66.12 27.72 90 top
CT18  0.1uF  [SMC0201A]  66.12 27.08 90 top
CT19  0.1uF  [SMC0201A]  66.12 26.45 90 top
CT20  0.1uF  [SMC0201A]  66 25.66 90 top
CT21  0.1uF  [SMC0201A]  66.02 25.13 90 top
CT22  0.1uF  [SMC0201A]  66.07 24.59 90 top
CT23  22uF  [SMC0603A]  55.17 15.37 90 top
CT24  22uF  [SMC0603A]  62.9 8.18 90 top
CT25  0.1uF  [SMC0201A]  3.45 6.5 180 top
CT28  0.1uF  [SMC0201A]  21.84 6.67 0 top
CT29  0.1uF  [SMC0402A]  38.97 6.28 90 top
CT30  0.1uF  [SMC0402A]  38.94 5.49 90 top
DST1  -  [SLEDR0603A]  66.26 38.89 0 top
DST2  -  [SLEDR0603B_CA]  67.66 36.99 180 top
EU5C1  -  [LCC20_16_5MC]  48.99 9.43 270 top
EU8F1  -  [LCC10_12_5MB]  49.19 42.91 90 bottom
EU12  -  [QFN32_20_5ML]  60.19 18.06 0 top
EUB1  -  [LCC8_32_24_127MA]  66.36 38.59 90 bottom
EUT1  -  [MLFP24_16_5MA]  13.56 14.64 180 top
EUT2  -  [LCC16_16_65MA]  5.56 10.44 90 top
EUT3  -  [TQFN28_16_4MB]  13.68 8.67 0 top
FB5C1  330  [SFB0603A]  45.13 6.63 0 bottom
FB11  30  [SFB0603A]  62.83 7.75 90 bottom
FB17  30  [SFB0603A]  64.74 16.41 90 top
FBB1  30  [SFB0603A]  57.22 36.48 270 bottom
FBB2  30  [SFB0603A]  60.04 33.69 180 bottom
FBB3  30  [SFB0603A]  25.24 26.29 180 bottom
FBB4  30  [SFB0603A]  65.5 29.62 90 bottom
FBB5  30  [SFB0805A]  13.3 23.91 180 bottom
FBB6  30  [SFB0603A]  66.44 26.5 0 bottom
FBB7  30  [SFB0805A]  5.94 19.97 90 bottom
FBB8  30  [SFB0603A]  62.45 24.8 270 bottom
FBB9  30  [SFB0805A]  50.77 14.25 0 bottom
FBB10  30  [SFB0805A]  65.83 14.31 180 bottom
FBB11  30  [SFB0805A]  3.78 12.35 0 bottom
FBB12  30  [SFB0603A]  30.32 12.6 270 bottom
FBB13  30  [SFB0603A]  29.05 12.6 90 bottom
J4  -  [SCONN20K_K70426001]  14.16 47.56 270 top
J8  -  [SCONN10_H39949001]  50.26 43.34 90 top
JT1  -  [SCONN14_D20995012]  59.91 43.34 90 top
JT3  -  [FCONN260_OCP_BMC]  1.43 1.57 0 top
NOREF  -  [unnamed]  67.6 6 0 top
NOREF#2  -  [unnamed]  2 6 0 top
Q3L1  -  [SOT363A]  6.19 43.71 0 bottom
Q6A1  -  [SOT23A]  2.63 48.29 270 bottom
Q7A1  -  [SOT23A]  9.49 48.16 180 bottom
QB1  -  [SOT363A]  66.82 33.08 90 bottom
QT1  -  [SOT363A]  16.24 25.18 270 top
R1A9  10.0K  [SMR0402A]  44.93 22.07 0 bottom
R1A11  10.0K  [SMR0402A]  45.92 22.32 0 bottom
R2A17  10.0K  [SMR0402A]  45.18 11.4 0 bottom
R2A21  100.0  [SMR0402A]  47.08 11.94 90 bottom
R2A22  100.0  [SMR0402A]  48.28 13.24 0 bottom
R2L48  0.0  [SMR0402A]  57.61 7.78 270 bottom
R2L54  0.0  [SMR0402A]  59.11 13.65 90 bottom
R3L1  4.75K  [SMR0402A]  8.98 44.61 180 bottom
R4L29  49.9  [SMR0402A]  2.38 28.61 90 top
R4L38  1.00K  [SMR0402A]  5.15 33.6 270 top
R4L39  49.9  [SMR0402A]  4.64 30.22 0 top
R4L40  10.0K  [SMR0402A]  4.97 28.6 270 top
R4L128  10.0K  [SMR0402A]  2.43 33.68 90 top
R5C3  200.0K  [SMR0603A]  49.82 12.86 270 top
R5C8  4.75K  [SMR0402A]  46.01 10.37 270 top
R5C13  4.75K  [SMR0402A]  48.93 11.21 90 bottom
R5C14  4.75K  [SMR0402A]  46.01 11.11 270 top
R5N6  0.0  [SMR0402A]  46.01 9.66 270 top
R7A1  1.00K  [SMR0402A]  10.76 47.53 0 bottom
R7A2  49.9  [SMR0402A]  12.29 44.54 180 bottom
R7A4  10.0K  [SMR0402A]  8.6 40.48 180 top
R7A52  10.0K  [SMR0402A]  61.31 9.54 180 top
R7A54  0  [SMR0201A]  61.5 11.11 270 top
R7A55  8.06K  [SMR0402A]  60.81 11.74 90 top
R7A57  1.0M  [SMR0402A]  58.63 13.65 90 top
R8A43  33.2  [SMR0402A]  58.39 6.32 0 top
R8A44  33.2  [SMR0402A]  53.63 7.45 270 top
R8A45  33.2  [SMR0402A]  53.63 6.71 270 top
R8A47  33.2  [SMR0402A]  54.76 9.37 0 bottom
R8A49  33.2  [SMR0402A]  53.49 9.09 0 top
R8A51  33.2  [SMR0402A]  53.55 9.81 270 top
R8A53  33.2  [SMR0402A]  53.47 10.57 270 top
R8A55  33.2  [SMR0402A]  53.45 11.33 270 top
R8A56  10.0  [SMR0402A]  53.55 12.1 270 top
R8A57  10.0  [SMR0402A]  53.55 12.86 270 top
R8A61  10.0  [SMR0402A]  53.46 11.96 180 bottom
R8A64  NA  [SMR0201A]  56.86 14.27 0 top
R8F1  10.0  [SMR0603A]  46.42 41.92 180 bottom
R8F3  10K  [SMR0201A]  49.98 41.69 270 bottom
R8F5  10K  [SMR0201A]  50.51 43.03 270 bottom
R8F6  0.0  [SMR0402A]  51.12 47.53 180 bottom
R8F7  10K  [SMR0201A]  48.89 48.04 180 bottom
R8F8  49.9  [SMR0402A]  48.13 47.61 90 bottom
R8F12  33.2  [SMR0402A]  49.65 47.66 0 bottom
R8L2  33.2  [SMR0402A]  3.97 43.97 270 bottom
R390  0  [SMR0201A]  56.13 5.91 0 top
R391  NA  [SMR0402A]  35.77 5.44 0 bottom
R392  0.0  [SMR0402A]  55.47 6.11 0 top
R393  10K  [SMR0201A]  9.59 10.75 90 top
R395  10.0K  [SMR0402A]  64.79 18.78 90 bottom
R396  0  [SMR0201A]  62.27 19.33 270 bottom
R397  8.06K  [SMR0402A]  63.9 19.82 270 bottom
R398  1.0M  [SMR0402A]  63.39 21.39 0 top
R399  33.2  [SMR0402A]  60.37 15.73 0 bottom
R400  33.2  [SMR0402A]  58.85 15.73 0 bottom
R401  33.2  [SMR0402A]  59.61 15.73 0 bottom
R402  33.2  [SMR0402A]  56.44 16.41 270 top
R403  33.2  [SMR0402A]  56.44 17.13 270 top
R404  33.2  [SMR0402A]  56.44 17.84 270 top
R405  33.2  [SMR0402A]  56.44 18.57 270 top
R406  33.2  [SMR0402A]  56.44 19.31 270 top
R407  10.0  [SMR0402A]  56.44 20.05 270 top
R408  10.0  [SMR0402A]  56.44 20.78 270 top
R409  10.0  [SMR0402A]  56.44 21.52 270 top
R410  NA  [SMR0201A]  59.94 20.15 0 bottom
R411  10K  [SMR0201A]  60.95 20.17 0 bottom
R412  0  [SMR0201A]  63.93 16.08 270 bottom
R413  0.0  [SMR0402A]  57.73 22.74 180 bottom
R414  0.0  [SMR0402A]  56.1 17.79 180 bottom
R415  120  [SMR0402A]  18.13 17.81 180 bottom
R416  120  [SMR0402A]  21.15 16.67 90 bottom
R417  4.02K  [SMR0402A]  52.16 22 0 top
R418  4.02K  [SMR0402A]  48.99 22 0 top
R419  4.02K  [SMR0402A]  49.24 19.8 0 top
R420  1.00K  [SMR0402A]  53.69 22 0 top
R421  1.00K  [SMR0402A]  48.23 22 0 top
R422  1.00K  [SMR0402A]  50.95 19.8 0 top
R423  2.0K  [SMR0402A]  51.4 22 0 top
R424  499.0  [SMR0402A]  52.93 22 0 top
R425  2.0K  [SMR0402A]  49.75 22 0 top
R426  499.0  [SMR0402A]  50.51 22 0 top
R427  2.0K  [SMR0402A]  50.08 19.8 0 top
R428  499.0  [SMR0402A]  51.81 19.8 0 top
R429  150.0  [SMR0402A]  52.67 19.83 0 top
R430  150.0  [SMR0402A]  48.22 19.77 270 top
R431  150.0  [SMR0402A]  48.19 19 270 top
R432  2.0K  [SMR0402A]  34.21 32.06 180 bottom
R433  2.0K  [SMR0402A]  33.45 32.06 180 bottom
R434  0.0  [SMR0402A]  45.15 13.52 90 top
R435  0.0  [SMR0402A]  46.6 11.89 90 top
R436  NA  [SMR0402A]  45.18 10.65 180 bottom
RB1  49.9  [SMR0201A]  43.27 48.02 0 bottom
RB2  49.9  [SMR0201A]  42.64 48.02 0 bottom
RB3  49.9  [SMR0201A]  42.13 48.02 0 bottom
RB4  49.9  [SMR0201A]  41.62 48.02 0 bottom
RB5  49.9  [SMR0201A]  41.12 48.02 0 bottom
RB6  49.9  [SMR0201A]  40.61 48.02 0 bottom
RB7  49.9  [SMR0201A]  40.1 48.02 0 bottom
RB8  49.9  [SMR0201A]  39.08 48.02 0 bottom
RB9  49.9  [SMR0201A]  38.58 48.02 0 bottom
RB10  49.9  [SMR0201A]  38.07 48.02 0 bottom
RB11  49.9  [SMR0201A]  37.56 48.02 0 bottom
RB12  49.9  [SMR0201A]  37.05 48.02 0 bottom
RB13  49.9  [SMR0201A]  36.04 48.02 0 bottom
RB14  49.9  [SMR0201A]  35.53 48.02 0 bottom
RB15  49.9  [SMR0201A]  35.02 48.02 0 bottom
RB16  49.9  [SMR0201A]  34.51 48.02 0 bottom
RB17  49.9  [SMR0201A]  34 48.02 0 bottom
RB18  10K  [SMR0201A]  66.82 36.3 180 bottom
RB19  49.9  [SMR0402A]  33.24 47.59 0 bottom
RB20  4.75K  [SMR0402A]  32.35 47.59 0 bottom
RB21  10.0K  [SMR0402A]  14.93 49.27 180 bottom
RB22  33.2  [SMR0402A]  55.57 40.7 180 bottom
RB23  2.0K  [SMR0402A]  45.15 47.68 0 top
RB24  10K  [SMR0201A]  54.88 39.12 0 bottom
RB25  10K  [SMR0201A]  13.61 36.37 180 top
RB26  33.2  [SMR0402A]  53.03 40.58 180 bottom
RB27  10K  [SMR0201A]  10.64 46.4 180 bottom
RB28  33.2  [SMR0402A]  53.74 40.58 180 bottom
RB29  10K  [SMR0201A]  63.82 37.06 0 bottom
RB30  49.9  [SMR0201A]  44.81 45.19 270 bottom
RB31  1.00K  [SMR0402A]  3.97 44.86 270 bottom
RB32  49.9  [SMR0201A]  44.81 44.66 270 bottom
RB33  10K  [SMR0201A]  53.64 38.46 0 bottom
RB34  10K  [SMR0201A]  11.19 27.25 180 top
RB35  10K  [SMR0201A]  65.96 47.12 90 bottom
RB36  49.9  [SMR0402A]  13.59 44.54 180 bottom
RB37  49.9  [SMR0201A]  44.79 43.57 270 bottom
RB38  10K  [SMR0201A]  66.36 37.06 0 bottom
RB39  49.9  [SMR0201A]  44.79 42.93 270 bottom
RB40  49.9  [SMR0201A]  44.76 42.4 270 bottom
RB41  49.9  [SMR0201A]  44.76 41.86 270 bottom
RB42  49.9  [SMR0201A]  44.79 41.33 270 bottom
RB43  240  [SMR0402A]  27.91 41.75 180 bottom
RB44  240  [SMR0402A]  18.13 41.75 180 bottom
RB45  240  [SMR0402A]  37.69 41.62 180 bottom
RB46  10K  [SMR0201A]  60.47 47.34 180 bottom
RB47  80.6  [SMR0402A]  39.49 40 0 bottom
RB48  10K  [SMR0201A]  58.11 47.99 0 bottom
RB49  10K  [SMR0201A]  60.47 43.68 0 bottom
RB50  240  [SMR0402A]  42.35 36.73 90 bottom
RB51  33.2  [SMR0402A]  56.74 44.16 0 top
RB52  33.2  [SMR0402A]  56.74 44.98 180 top
RB53  1.0K  [SMR0201A]  57.58 43.27 180 top
RB54  33.2  [SMR0402A]  57.22 48.47 180 bottom
RB55  33.2  [SMR0402A]  52.44 33 180 bottom
RB56  240  [SMR0402A]  39.59 33.24 180 bottom
RB57  240  [SMR0402A]  38.83 32.35 0 bottom
RB58  10K  [SMR0201A]  42.77 32.94 180 bottom
RB59  10K  [SMR0201A]  42.15 32.94 180 bottom
RB60  10K  [SMR0201A]  41.62 32.94 180 bottom
RB61  10K  [SMR0201A]  41.12 32.94 180 bottom
RB62  10K  [SMR0201A]  38.02 32.94 180 bottom
RB63  10K  [SMR0201A]  37.43 32.94 180 bottom
RB64  10K  [SMR0201A]  36.92 32.94 180 bottom
RB65  10K  [SMR0201A]  36.42 32.94 180 bottom
RB68  10K  [SMR0201A]  66.19 35.79 0 bottom
RB69  33.2  [SMR0402A]  49.78 35.9 90 bottom
RB70  33.2  [SMR0402A]  49.55 33.62 0 bottom
RB71  10K  [SMR0201A]  51.89 35.1 180 bottom
RB72  49.9K  [SMR0201A]  40.04 27.03 90 bottom
RB73  49.9K  [SMR0201A]  12.36 6.23 180 bottom
RB74  240  [SMR0402A]  17.27 27.12 180 bottom
RB75  10.0K  [SMR0402A]  36.25 26.62 270 bottom
RB77  0.0  [SMR0402A]  41.47 25.98 180 bottom
RB78  10K  [SMR0201A]  16.95 25.25 270 bottom
RB79  10.0K  [SMR0402A]  16 18.4 180 top
RB80  53.6K  [SMR0402A]  4.68 24.06 90 bottom
RB81  1.00K  [SMR0402A]  6.13 24.03 270 bottom
RB82  49.9K  [SMR0201A]  11.7 6.23 180 bottom
RB84  10.0  [SMR0402A]  15.72 23.36 0 bottom
RB85  10.0K  [SMR0402A]  56.74 29.43 0 bottom
RB86  0.0  [SMR0402A]  47.53 23.17 90 bottom
RB87  NA  [SMR0402A]  55 29.37 270 bottom
RB88  2.0K  [SMR0402A]  18.05 22.31 0 bottom
RB89  0.0  [SMR0402A]  22 22.76 270 bottom
RB90  0.0  [SMR0402A]  43.15 23.03 180 bottom
RB91  10K  [SMR0201A]  56.88 28.73 90 bottom
RB92  0.0  [SMR0402A]  7.14 22.51 90 bottom
RB93  47K  [SMR0402A]  5.49 22.51 90 bottom
RB94  100.0K  [SMR0402A]  46.64 22.41 270 bottom
RB95  10K  [SMR0201A]  18.81 22.94 0 bottom
RB96  10K  [SMR0201A]  57.88 28.49 180 bottom
RB97  10K  [SMR0201A]  56.88 28.1 90 bottom
RB98  33.2  [SMR0402A]  41.23 21.47 270 bottom
RB99  NA  [SMR0402A]  21.94 20.92 0 bottom
RB100  33.2  [SMR0402A]  56.38 24 0 bottom
RB101  33.2  [SMR0402A]  55.59 24 0 bottom
RB102  10K  [SMR0201A]  41.08 20.35 270 bottom
RB103  33.2  [SMR0402A]  22.69 20.2 90 bottom
RB104  10K  [SMR0201A]  43 19.73 0 bottom
RB105  10K  [SMR0201A]  43.58 19.7 0 bottom
RB106  10K  [SMR0201A]  41.08 19.84 270 bottom
RB107  33.2  [SMR0402A]  64.04 25.81 90 bottom
RB108  0.0  [SMR0402A]  32.75 19.36 90 bottom
RB109  10K  [SMR0201A]  41.05 19.33 270 bottom
RB110  33.2  [SMR0402A]  57.88 23.79 0 bottom
RB111  33.2  [SMR0402A]  61.49 23.82 0 bottom
RB112  0.0  [SMR0402A]  40.77 18.06 270 bottom
RB113  0.0  [SMR0402A]  12.86 18.19 90 bottom
RB114  22.1K  [SMR0402A]  5.24 18.19 270 bottom
RB115  33.2  [SMR0402A]  59.91 23.79 0 bottom
RB116  10K  [SMR0201A]  41.15 17.46 270 bottom
RB117  47K  [SMR0402A]  6.13 17.43 90 bottom
RB118  33.2  [SMR0402A]  60.7 23.82 0 bottom
RB119  0.0  [SMR0402A]  41.15 16.67 270 bottom
RB120  0.0  [SMR0402A]  7.27 16.41 90 bottom
RB121  200.0K  [SMR0402A]  54.58 15.91 270 bottom
RB122  0.0  [SMR0402A]  41.18 15.93 270 bottom
RB123  33.2  [SMR0402A]  36.51 15.09 90 bottom
RB124  200.0K  [SMR0402A]  55.47 15.14 90 bottom
RB125  0.0  [SMR0402A]  41.2 15.14 270 bottom
RB126  NA  [SMR0402A]  35.53 15.92 0 bottom
RB127  10.0K  [SMR0402A]  53.69 14.45 0 bottom
RB128  0.0  [SMR0402A]  52.8 15.33 180 bottom
RB129  0.0  [SMR0402A]  54.58 14.38 270 bottom
RB130  49.9K  [SMR0201A]  41.79 14.53 90 bottom
RB131  49.9K  [SMR0201A]  41.79 13.98 90 bottom
RB132  4.75K  [SMR0402A]  11.66 13.48 0 bottom
RB133  10K  [SMR0201A]  43.17 13.61 0 bottom
RB134  0.0  [SMR0402A]  41.66 13.11 270 bottom
RB135  10K  [SMR0201A]  34.27 13.11 90 bottom
RB136  4.75K  [SMR0402A]  15.32 12.64 0 bottom
RB137  4.75K  [SMR0402A]  14.43 12.64 0 bottom
RB138  10K  [SMR0201A]  41.56 12.38 270 bottom
RB139  49.9K  [SMR0201A]  42.12 11.79 90 bottom
RB140  33.2  [SMR0402A]  7.61 12.06 180 bottom
RB141  0.0  [SMR0402A]  63.8 12.01 180 bottom
RB142  10.0K  [SMR0402A]  62.91 11.12 0 bottom
RB143  10K  [SMR0201A]  15.03 23.55 0 bottom
RB144  NA  [SMR0402A]  11.21 11.21 270 bottom
RB145  NA  [SMR0402A]  3.33 11.21 270 bottom
RB146  4.75K  [SMR0402A]  11.21 10.44 270 bottom
RB147  NA  [SMR0402A]  9.05 10.44 270 bottom
RB148  10K  [SMR0201A]  46.15 10.98 180 bottom
RB149  NA  [SMR0402A]  15.59 9.87 0 bottom
RB150  NA  [SMR0402A]  13.94 10.64 180 bottom
RB151  4.75K  [SMR0402A]  13.05 10.64 180 bottom
RB152  4.75K  [SMR0402A]  11.21 9.68 270 bottom
RB153  NA  [SMR0402A]  9.05 9.68 270 bottom
RB154  49.9K  [SMR0201A]  40.96 9.12 90 bottom
RB155  100.0K  [SMR0402A]  64.59 9.49 180 bottom
RB156  200.0K  [SMR0402A]  63.82 8.6 0 bottom
RB157  0.0  [SMR0402A]  63.06 9.49 180 bottom
RB158  10K  [SMR0201A]  7.82 9.24 180 bottom
RB159  NA  [SMR0402A]  11.21 8.92 270 bottom
RB160  4.75K  [SMR0402A]  9.05 8.92 270 bottom
RB161  15  [SMR0201A]  6.46 8.79 90 bottom
RB162  0  [SMR0805A]  3.78 7.9 0 bottom
RB163  NA  [SMR0402A]  11.21 8.16 270 bottom
RB164  4.75K  [SMR0402A]  9.05 8.16 270 bottom
RB165  NA  [SMR0402A]  11.21 7.4 270 bottom
RB166  4.75K  [SMR0402A]  9.05 7.4 270 bottom
RB167  2.0K  [SMR0402A]  18.29 7.42 90 bottom
RB168  10.0  [SMR0402A]  29.62 7.24 270 bottom
RB169  10.0K  [SMR0402A]  23.98 6.15 270 bottom
RB171  15  [SMR0201A]  5.66 5.83 0 bottom
RB172  0.0  [SMR0402A]  60.92 5.85 270 bottom
RB173  0.0  [SMR0402A]  60.2 5.85 90 bottom
RB175  10.0K  [SMR0402A]  38.02 6.39 180 bottom
RB177  0.0  [SMR0402A]  36.49 6.39 180 bottom
RB178  1.00K  [SMR0402A]  41.55 6.37 180 bottom
RB179  49.9K  [SMR0201A]  32.45 6.42 180 bottom
RB180  200.0  [SMR0402A]  30.35 5.45 0 bottom
RB181  0.0  [SMR0402A]  29.61 6.34 180 bottom
RB182  49.9K  [SMR0201A]  32.96 6.42 180 bottom
RB183  33.2  [SMR0402A]  64.03 5.4 0 bottom
RB184  0.0  [SMR0402A]  57.71 5.85 270 bottom
RB185  4.75K  [SMR0402A]  9.26 6.29 180 bottom
RB186  33.2  [SMR0402A]  63.19 4.21 0 bottom
RB187  49.9  [SMR0201A]  30.96 5.35 0 bottom
RB188  10K  [SMR0201A]  65.55 5.33 0 bottom
RB189  10K  [SMR0201A]  64.99 5.33 0 bottom
RB190  10K  [SMR0201A]  33.7 5.06 0 bottom
RB191  0.0  [SMR0402A]  56.29 4.96 270 bottom
RT1  1.0K  [SMR0201A]  12.64 41.47 0 top
RT2  33.2  [SMR0402A]  2.32 41.18 90 top
RT3  10K  [SMR0201A]  10.48 40.91 180 top
RT4  10K  [SMR0201A]  11.54 40.91 180 top
RT5  10K  [SMR0201A]  14.54 40.91 180 top
RT6  33.2  [SMR0402A]  5.05 41.12 0 top
RT7  33.2  [SMR0402A]  5.94 41.12 0 top
RT8  33.2  [SMR0402A]  6.83 41.12 0 top
RT9  33.2  [SMR0402A]  7.71 41.12 0 top
RT10  0  [SMR0201A]  56.64 42.49 180 bottom
RT11  10K  [SMR0201A]  11.5 34.69 180 top
RT12  10.0  [SMR0402A]  14.51 34.12 270 top
RT13  10.0  [SMR0402A]  6.99 33.81 270 top
RT14  10.0  [SMR0402A]  9.24 33.11 180 top
RT15  10.0  [SMR0402A]  11.52 33.88 0 top
RT16  10.0  [SMR0402A]  12.54 33.88 0 top
RT18  10.0  [SMR0402A]  6.97 33.08 270 top
RT20  10.0K  [SMR0402A]  17.27 12.48 0 bottom
RT21  10K  [SMR0201A]  7.49 30.8 180 top
RT23  10K  [SMR0201A]  41.55 30.3 180 top
RT24  10K  [SMR0201A]  42.89 30.33 0 top
RT25  10K  [SMR0201A]  44.16 29.85 180 top
RT27  10.0  [SMR0402A]  7.47 30.1 270 top
RT28  10K  [SMR0201A]  46.78 35.34 90 bottom
RT30  10.0  [SMR0402A]  7.42 28.94 270 top
RT31  221  [SMR0402A]  66.01 35.72 0 top
RT32  221  [SMR0402A]  66.74 35.72 0 top
RT33  10K  [SMR0201A]  41.56 28.66 90 top
RT34  10K  [SMR0201A]  46.78 34.75 90 bottom
RT35  10K  [SMR0201A]  41.56 28.15 90 top
RT36  10K  [SMR0201A]  7.41 27.7 0 top
RT37  33.2  [SMR0402A]  47.31 35.03 270 top
RT38  10.0  [SMR0402A]  8.45 26.87 180 top
RT39  0.0  [SMR0402A]  15.98 27.31 270 top
RT40  10.0  [SMR0402A]  10.13 26.89 180 top
RT41  10.0  [SMR0402A]  12.36 26.99 180 top
RT42  10K  [SMR0201A]  65.88 33.3 90 top
RT43  10K  [SMR0201A]  11.75 27.25 180 top
RT44  33.2  [SMR0402A]  46.07 32.01 90 top
RT45  10.0K  [SMR0402A]  15.91 26.32 270 top
RT46  10K  [SMR0201A]  8.52 26.07 270 top
RT47  2.0K  [SMR0402A]  46.96 31.02 270 top
RT48  33.2  [SMR0402A]  65.94 31.65 90 top
RT49  2.0K  [SMR0402A]  46.96 30.13 270 top
RT50  0.0  [SMR0402A]  3.33 24.54 270 top
RT51  0.0  [SMR0402A]  6.64 24.54 270 top
RT52  10.0K  [SMR0402A]  4.1 24.05 90 top
RT53  10.0K  [SMR0402A]  12.79 24.48 0 top
RT57  10K  [SMR0201A]  41.36 20.22 90 top
RT58  1.0K  [SMR0201A]  46.26 20.07 270 top
RT59  10K  [SMR0201A]  41.36 19.72 90 top
RT60  1.0K  [SMR0201A]  46.26 19.18 270 top
RT61  10.0K  [SMR0402A]  3.46 18.57 90 top
RT62  0.0  [SMR0402A]  5.56 18.89 0 top
RT63  10.0K  [SMR0402A]  14.24 18.87 0 top
RT64  237.0K  [SMR0402A]  10.71 18.84 0 top
RT65  200.0K  [SMR0402A]  11.6 17.95 180 top
RT66  0.0  [SMR0402A]  12.49 18.84 0 top
RT67  0.0  [SMR0402A]  13.38 17.95 180 top
RT68  33.2  [SMR0402A]  41.28 18.27 90 top
RT69  1.00K  [SMR0402A]  6.32 18.19 90 top
RT70  10K  [SMR0201A]  41.26 17.56 90 top
RT71  10K  [SMR0201A]  52.88 23.55 0 bottom
RT72  10K  [SMR0201A]  41.66 16.62 90 top
RT73  NA  [SMR0402A]  63.93 22.14 180 top
RT74  33.2  [SMR0402A]  16.43 15.87 180 top
RT75  10.0K  [SMR0402A]  62.33 23.03 0 top
RT76  NA  [SMR0402A]  61.59 22.17 180 top
RT78  10.0K  [SMR0402A]  18.97 21.01 90 bottom
RT79  10.0K  [SMR0402A]  58.64 22.17 180 top
RT80  NA  [SMR0402A]  59.38 23.06 0 top
RT81  10.0K  [SMR0402A]  60.12 23.06 0 top
RT82  NA  [SMR0402A]  60.88 22.17 180 top
RT83  10.0K  [SMR0402A]  63.09 23.03 0 top
RT84  10.0K  [SMR0402A]  64.76 22.14 180 top
RT85  NA  [SMR0402A]  65.6 23.03 0 top
RT86  10K  [SMR0201A]  41.66 16.06 90 top
RT87  10K  [SMR0201A]  56.58 22.27 180 top
RT88  10K  [SMR0201A]  41.64 15.52 90 top
RT89  10K  [SMR0201A]  44.04 14.78 180 top
RT90  10K  [SMR0201A]  41.64 15.02 90 top
RT91  10K  [SMR0201A]  57.88 14.27 0 top
RT92  2.0K  [SMR0402A]  45.18 14.31 180 top
RT93  10K  [SMR0201A]  41.32 13.89 0 top
RT94  10.0K  [SMR0402A]  9.18 12.98 270 top
RT95  33.2  [SMR0402A]  45.12 12.68 90 top
RT96  10.0K  [SMR0402A]  9.18 12.1 270 top
RT97  2.0K  [SMR0402A]  46.01 11.89 270 top
RT98  10K  [SMR0201A]  7.79 33.37 0 top
RT99  10K  [SMR0201A]  6.5 34.92 180 top
RT100  10K  [SMR0201A]  9.11 10.56 0 top
RT101  15  [SMR0201A]  9 9.17 270 top
RT102  0.0  [SMR0402A]  46.01 8.92 270 top
RT103  NA  [SMR0402A]  44.48 7.73 90 top
RT104  NA  [SMR0402A]  42.51 7.89 0 top
RT105  1.00K  [SMR0402A]  43.71 7 180 top
RT106  10K  [SMR0201A]  7.08 7.54 0 top
RT107  10K  [SMR0201A]  7.79 7.41 0 top
RT108  49.9K  [SMR0201A]  41.07 6.85 180 top
RT109  1.00K  [SMR0402A]  45.37 6.97 270 top
RT112  49.9K  [SMR0201A]  22.4 6.67 0 top
RT113  0  [SMR0603A]  30.21 6.38 90 top
RT114  10K  [SMR0201A]  32.58 6.11 180 top
RT115  0.0  [SMR0402A]  28.66 6.23 270 top
RT116  0  [SMR0805A]  4.41 6.13 90 top
RT117  0.0  [SMR0402A]  48.38 6.48 0 top
RT118  0.0  [SMR0402A]  49.24 6.48 0 top
RT122  4.75K  [SMR0402A]  9.14 6.32 0 top
RT123  4.75K  [SMR0402A]  34.26 6.32 0 top
RT128  33.2  [SMR0402A]  61.84 5.36 180 top
RT129  33.2  [SMR0402A]  63.98 5.4 180 top
RT130  1.00K  [SMR0402A]  42.11 6.29 0 top
RT131  NA  [SMR0402A]  42.82 5.4 180 top
RT132  33.2  [SMR0402A]  64.86 5.4 180 top
RT133  33.2  [SMR0402A]  63.11 5.38 180 top
RT134  15  [SMR0201A]  3.45 5.35 180 top
RT135  NA  [SMR0201A]  35.15 5.35 180 top
RT136  NA  [SMR0201A]  35.78 5.35 180 top
RT137  10K  [SMR0201A]  37.73 25.79 270 bottom
RT138  NA  [SMR0402A]  10.67 25.3 270 top
RT139  NA  [SMR0402A]  14.48 35.69 270 top
RT140  NA  [SMR0402A]  10.67 26.09 270 top
S7A1  -  [SSW2RPB]  14.32 38.89 270 top
S7A2  -  [SSW2RPB]  3.75 39.5 0 top
ST1  -  [SSW04RDA]  44.15 20.99 180 top
TP1  -  [TP_R30X35T]  68.17 35.46 270 top
TP2  -  [TP_R30X35B]  68.17 35.46 270 top
TP3  -  [TP_R30X35T]  68.17 34.19 270 top
TP4  -  [TP_R30X35B]  68.17 34.19 270 top
TP5  -  [TP_R30X35T]  68.17 32.92 270 top
TP6  -  [TP_R30X35B]  68.17 32.92 270 top
TP7  -  [TP_R30X35T]  68.17 31.65 270 top
TP8  -  [TP_R30X35B]  68.17 31.65 270 top
U2  -  [FBGA96_3_8MC]  20.13 40.03 180 top
U3  -  [FBGA96_3_8MC]  29.97 40.01 180 top
U4  -  [FBGA96_3_8MC]  39.75 39.96 180 top
U7  -  [SSOP6_53_65MB]  43.9 24.29 90 bottom
U8  -  [SSOP5_53_65MA]  26.08 6.14 0 bottom
U8A6  -  [QFN32_20_5ML]  57.24 10.32 0 top
U12  -  [QFN16_14_16_5MB]  57.88 44.96 270 bottom
UB1  -  [SSOP6_53_65MB]  12.29 48.16 270 bottom
UB2  -  [SSOP6_53_65MA]  53.73 46.46 90 bottom
UB3  -  [SSOP6_53_65MA]  53.73 42.4 90 bottom
UB4  -  [BGA100_2_1MA]  8.98 33.97 180 bottom
UB5  -  [SSOP8_45_65MA]  45.22 20.03 270 bottom
UT1  -  [SSOP6_53_65MB]  3.83 32.4 270 top
UT2  -  [SSOP6_67_95MA]  13.93 29.04 90 top
UT3  -  [SSOP6_67_95MA]  2.76 27.4 0 top
UT4  -  [BGA256_1_1MB]  63.88 25.02 180 top
UT5  -  [MPM3632]  5.94 21.24 90 top
UT6  -  [MPM3833]  13.17 21.11 90 top
UT7  -  [BGA672_2_8MX]  29.18 19.21 90 top
UT8  -  [MPM3632]  5.94 15.65 90 top
UT9  -  [MPM3804]  53.03 15.11 0 top
UT10  -  [SSOP8_12_65MB]  43.94 13.27 270 top
UT11  -  [MPM3804]  63.84 10.29 270 top
Y2  -  [SMY1310A]  66.58 20.34 270 top
Y7A1  -  [SMY1310A]  64.37 14.37 270 top
YT1  -  [SMY1310A]  48.67 16.53 270 top

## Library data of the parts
C1A6-C1A8 C9L13 CB19-CB21 = CAP: alternate symbols: (); part number: CAP_0201-0.1UF,6.3V,10%,X6S,C71412-003; tolerance: 10%; room: SM_MEM
C2L16 C2L18 C2L24-C2L26 C2L31 C2L34 C8A30 C8A31 C308-C310 C312-C317 = CAP: alternate symbols: (); part number: CAP_0201-0.1UF,6.3V,10%,X6S,C71412-003; tolerance: 10%; room: SMC_USB
C2L17 C3L11 C7A14 C8A32 C305 C311 C318 C320 = CAP: alternate symbols: (SMX0402,SMX0402A,SMX0402B,SMX0402C); part number: CAP_0402-2.2UF,6.3V,20%,X6S,D97712-006; tolerance: 20%; room: SMC_USB
C5C1 C5C2 C5C8 C5C13 C5N17 = CAP: alternate symbols: (); part number: CAP_0201-0.1UF,6.3V,10%,X6S,C71412-003; tolerance: 10%; room: SI5338
C5C5 C5C6 = CAP: alternate symbols: (SMX0402,SMX0402A,SMX0402B); part number: CAP_0402-33.0PF,50V,5%,EMPTY,A36095-031; tolerance: 5%; room: SI5338
C5C7 = CAP: alternate symbols: (SMX0402C,SMX0402D); part number: CAP_0402-10UF,6.3V,20%,X6S,H80885-001; tolerance: 20%; room: SI5338
C7A15 C319 = CAP: alternate symbols: (SMX0402,SMX0402A,SMX0402B); part number: CAP_0402-1.0UF,10V,10%,X6S,D97712-005; tolerance: 10%; room: SMC_USB
C7A16 C7A17 C306 C307 = CAP: alternate symbols: (SMX0402,SMX0402A,SMX0402B); part number: CAP_0402LF-22.0PF,50V,5%,COG,A36095-030; tolerance: 5%; room: SMC_USB
C8F1 C8F3 = CAP: alternate symbols: (SMX0402C,SMX0402D); part number: CAP_0402-10UF,6.3V,20%,X6S,H80885-001; tolerance: 20%; room: VTT_CPU0_ABC_PWR_VR
C8F2 = CAP: alternate symbols: (SMX0603); part number: CAP_0603-22UF,6.3V,20%,X6S,H63299-001; tolerance: 20%; room: VTT_CPU1_ABC_PWR_VR
C8F4 = CAP: alternate symbols: (SMX0402,SMX0402A,SMX0402B); part number: CAP_0402-1.0UF,10V,10%,X6S,D97712-005; tolerance: 10%; room: VTT_CPU1_ABC_PWR_VR
C8F5 = CAP: part number: CAP_0603-4.7UF,6.3V,10%,X7R,G10601-005; tolerance: 10%; room: VTT_CPU1_ABC_PWR_VR
C8F6 = CAP: alternate symbols: (SMX0402,SMX0402A,SMX0402B); part number: CAP_0402LF-0.1UF,16V,10%,X7R,A36096-030; tolerance: 10%; room: PVCCIN_CPU0_CTRL
C8F7 C8F8 = CAP: alternate symbols: (SMX0402,SMX0402A,SMX0402B); part number: CAP_0402LF-1000PF,50V,10%,X7R,A36096-046; tolerance: 10%; room: VTT_CPU0_ABC_PWR_VR
C107 C114 CB112 CB131 CB169 CB182 = CAP: alternate symbols: (SMX0603); part number: CAP_0603-10UF,16V,20%,X6S,656725-013; tolerance: 20%
C321 CB14 CB74 CB121 CB124 CB132 CB154 CB187 CB199 CB201 CB207-CB209 CB212 CT10 CT14 = CAP: alternate symbols: (SMX0402,SMX0402A,SMX0402B); part number: CAP_0402-1.0UF,10V,10%,X6S,D97712-005; tolerance: 10%
C322 CB4-CB13 CB15 CB16 CB25 CB27-CB31 CB34 CB35 CB37-CB40 CB42-CB50 CB56-CB58 CB60-CB62 CB64 CB66-CB70 CB72 CB75 CB78-CB80 CB82-CB85 CB88 CB89 CB91 CB96-CB101 CB103 CB104 CB108-CB110 CB116-CB120 CB122 CB128 CB129 CB133 CB136-CB141 CB143 CB172 CB179 CB188 CB206 CB210 CT11-CT13 CT15-CT22 CT25 = CAP: alternate symbols: (); part number: CAP_0201-0.1UF,6.3V,10%,X6S,C71412-003; tolerance: 10%
CB1 CT29 CT30 = CAP: alternate symbols: (SMX0402,SMX0402A,SMX0402B); part number: CAP_0402LF-0.1UF,16V,10%,X7R,A36096-030; tolerance: 10%
CB2 CB17 CB22 CB23 CB33 CB51 CB55 CT7 = CAP: part number: CAP_0201-10PF,50V,5%,C0G,D70542-078; tolerance: 5%
CB3 CB52-CB54 CB160 = CAP: alternate symbols: (SMX0402C,SMX0402D); part number: CAP_0402-10UF,6.3V,20%,X6S,H80885-001; tolerance: 20%
CB18 CB73 CB76 CB77 CB90 CB92-CB94 CB102 CB105-CB107 CB111 CB113 CB114 CB123 CB130 CB134 CB135 CB150 CB156 CB158 CB161 CB162 CB165 CB170 CB175 CB181 CB183 CB189 CB190 CB192 CB193 CB195 CB196 CB200 CB203 CB205 = CAP: part number: CAP_0201-0.01UF,10V,10%,X7R,D70538-003; tolerance: 10%
CB24 CB26 CB32 = CAP: part number: CAP_0201-0.01UF,10V,10%,X7R,D70538-003; tolerance: 10%; room: SM_MEM
CB36 CB41 CB197 CT2 = CAP: alternate symbols: (); part number: CAP_0201-0.1UF,6.3V,10%,X6S,C71412-003; tolerance: 10%; room: FPGA
CB59 CB63 CB65 CB71 CB86 CB142 = CAP: alternate symbols: (SMX0402,SMX0402A,SMX0402B,SMX0402C); part number: CAP_0402-2.2UF,6.3V,20%,X6S,D97712-006; tolerance: 20%
CB81 CB213 CT28 = CAP: alternate symbols: (); part number: CAP_0201-0.1UF,6.3V,10%,X6S,C71412-003; tolerance: 10%; room: SMC_VOL_TRANSLATOR
CB87 = CAP: part number: CAP_0603-4.7UF,6.3V,10%,X7R,G10601-005; tolerance: 10%
CB95 CB149 CB177 CB198 CB211 = CAP: alternate symbols: (SMX0402,SMX0402A,SMX0402B); part number: CAP_0402-0.47UF,16V,10%,X7R,G23339-001; tolerance: 10%
CB115 CB125 CB126 CB144-CB146 CB163 CB164 CT23 CT24 = CAP: alternate symbols: (SMX0603); part number: CAP_0603-22UF,6.3V,20%,X6S,H63299-001; tolerance: 20%
CB127 CB147 CB166 CB173 CB184 = CAP: alternate symbols: (SMX0402,SMX0402A,SMX0402B); part number: CAP_0402-0.1UF,16V,10%,X7R,A36096-030; tolerance: 10%
CB148 CB151 CB157 CB159 CB167 CB168 CB174 CB176 CB178 CB180 CB191 CB194 CB202 = CAP: part number: CAP_0201-22NF,4V,20%,X6S,A95538-005; tolerance: 20%
CB152 CB171 = CAP: part number: CAP_0805-100UF,4V,20%,X6S,H94455-002; tolerance: 20%
CB153 CB155 = CAP: alternate symbols: (SMX0402,SMX0402A,SMX0402B); part number: CAP_0402-0.220UF,16V,10%,X7R,A36096-104; tolerance: 10%
CB185 CB186 = CAP: alternate symbols: (); part number: CAP_0201-0.1UF,6.3V,10%,X6S,C71412-003; tolerance: 10%; room: SYS_FAN_CONTROLLER
